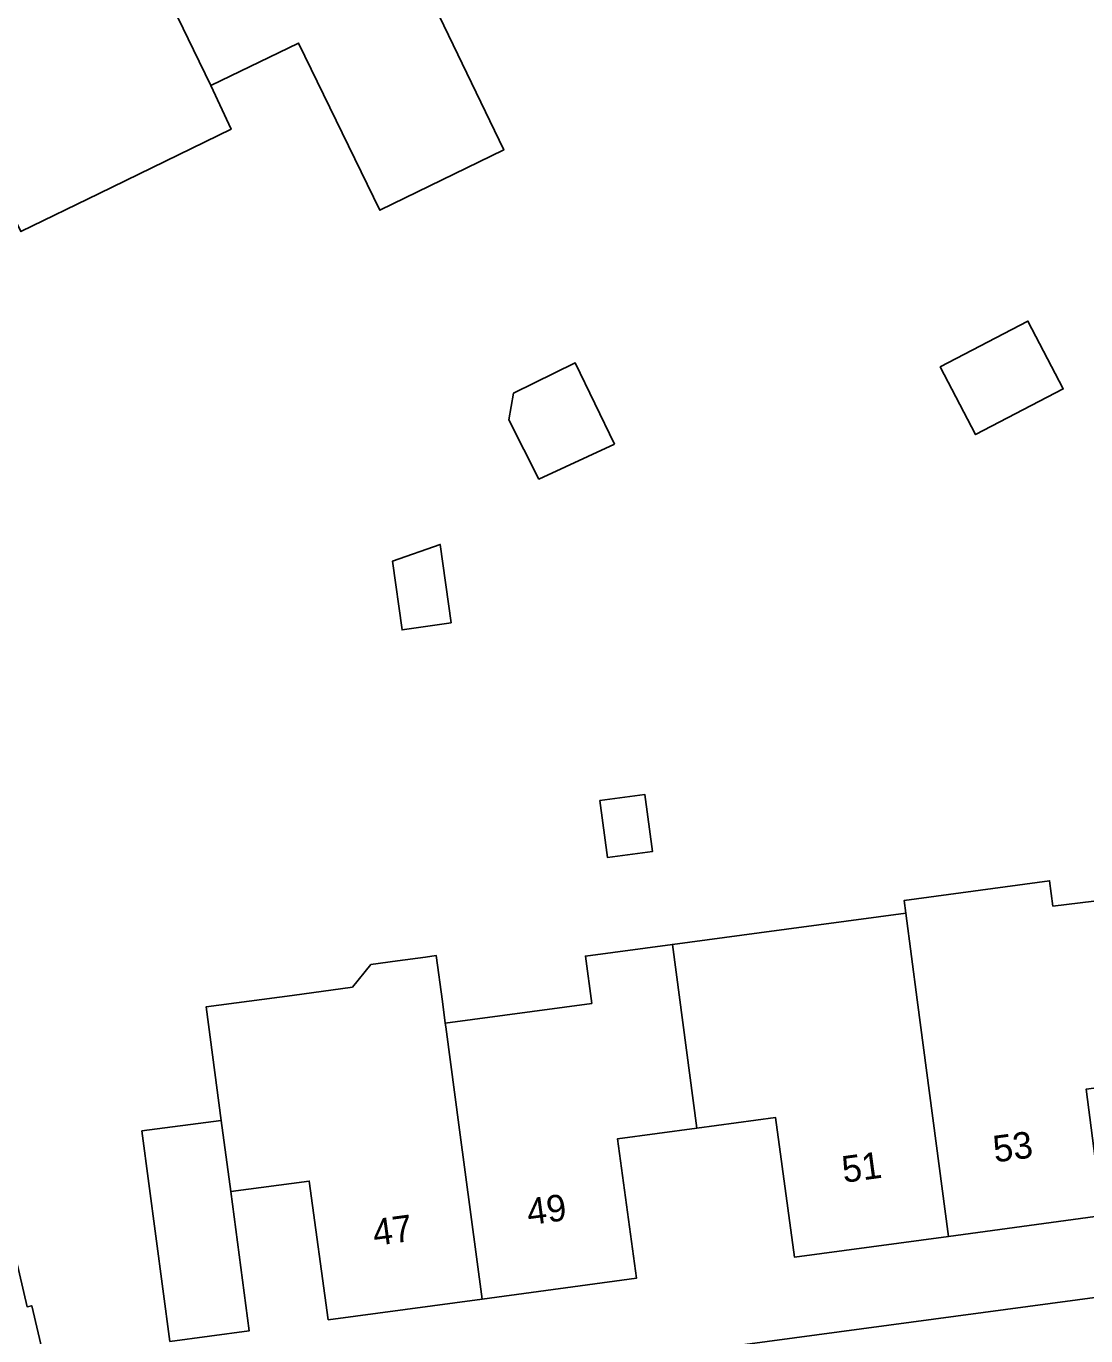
# Model space of a CAD drawing. Extents: x 163426 to 164192, y 380329 to 381641.
# Drawn here: x 163600.88 to 163640.74, y 381284.84 to 381334.12 of the extents above; entities that cross this region are included whole.
import ezdxf

# ---------------------------------------------------------------- set-up
doc = ezdxf.new("R2010")
doc.units = 0
for name, color, linetype in [('IMGEO_Erf', 7, 'Continuous'), ('IMGEO_Pand', 7, 'Continuous'), ('IMGEO_Pand_nummerreeks', 7, 'Continuous'), ('IMGEO_Voetpad_open', 7, 'Continuous')]:
    doc.layers.add(name, color=color, linetype=linetype)

msp = doc.modelspace()

# ---------------------------------------------------------------- linework, layer by layer
at = {"layer": 'IMGEO_Erf'}
for points in [[(163616.584, 381334.147), (163618.845, 381329.461), (163614.183, 381327.191), (163611.124, 381333.487), (163607.829, 381331.883), (163608.59, 381330.244), (163603.63, 381327.83), (163600.68, 381326.39)], [(163641.37, 381289.36), (163635.572, 381288.579), (163629.776, 381287.799), (163629.07, 381293.049), (163626.1, 381292.65), (163623.127, 381292.25), (163623.833, 381287), (163618.037, 381286.22), (163612.24, 381285.44), (163611.53, 381290.66), (163608.572, 381290.266), (163609.266, 381285.022), (163606.284, 381284.627), (163605.236, 381292.548), (163608.214, 381292.942), (163607.65, 381297.21), (163610.885, 381297.648), (163613.152, 381297.952), (163613.845, 381298.813), (163614.843, 381298.947), (163615.896, 381299.088), (163616.304, 381299.143), (163616.535, 381297.422), (163616.645, 381296.602), (163622.155, 381297.342), (163621.916, 381299.124), (163625.186, 381299.562), (163628.45, 381300), (163633.97, 381300.741), (163633.908, 381301.222), (163639.372, 381301.961), (163639.5, 381301.01), (163642.07, 381301.32)], [(163599.791, 381290.734), (163600.912, 381285.927), (163601.092, 381285.969), (163601.704, 381283.347)], [(163588.634, 381279.227), (163596.717, 381280.313), (163605.786, 381281.532), (163642.098, 381286.411), (163645.301, 381286.841)]]:
    msp.add_lwpolyline(points, dxfattribs=at)
for points in [[(163639.888, 381320.472), (163636.593, 381318.749), (163635.261, 381321.298), (163638.556, 381323.021)], [(163623.007, 381318.389), (163620.168, 381317.076), (163619.036, 381319.31), (163619.216, 381320.316), (163621.535, 381321.449)], [(163616.871, 381311.662), (163615.022, 381311.401), (163614.658, 381313.987), (163616.455, 381314.619)], [(163624.156, 381305.204), (163624.44, 381303.062), (163622.746, 381302.835), (163622.463, 381304.977)]]:
    msp.add_lwpolyline(points, close=True, dxfattribs=at)
at = {"layer": 'IMGEO_Pand'}
for points in [[(163613.542, 381340.434), (163610.85, 381339.112), (163608.422, 381344.055), (163607.84, 381345.24), (163605.28, 381344), (163605.938, 381342.655), (163603.253, 381341.342), (163607.177, 381333.232), (163607.829, 381331.883), (163611.124, 381333.487), (163614.183, 381327.191), (163618.845, 381329.461), (163616.584, 381334.147)], [(163603.253, 381341.342), (163600.558, 381340.025), (163599.9, 381341.37), (163597.36, 381340.12), (163600.326, 381333.998), (163597.625, 381332.689), (163598.149, 381331.624), (163600.68, 381326.39), (163603.63, 381327.83), (163608.59, 381330.244), (163607.829, 381331.883), (163607.177, 381333.232)], [(163635.261, 381321.298), (163636.593, 381318.749), (163639.888, 381320.472), (163638.556, 381323.021)], [(163623.007, 381318.389), (163621.535, 381321.449), (163619.216, 381320.316), (163619.036, 381319.31), (163620.168, 381317.076)], [(163616.871, 381311.662), (163616.455, 381314.619), (163614.658, 381313.987), (163615.022, 381311.401)], [(163622.463, 381304.977), (163622.746, 381302.835), (163624.44, 381303.062), (163624.156, 381305.204)], [(163642.07, 381301.32), (163639.5, 381301.01), (163639.372, 381301.961), (163633.908, 381301.222), (163633.97, 381300.741), (163634.391, 381297.478), (163635.572, 381288.579), (163641.37, 381289.36), (163640.75, 381294.12), (163644.78, 381294.65)], [(163634.391, 381297.478), (163633.97, 381300.741), (163628.45, 381300), (163625.186, 381299.562), (163626.1, 381292.65), (163629.07, 381293.049), (163629.776, 381287.799), (163635.572, 381288.579)], [(163625.186, 381299.562), (163621.916, 381299.124), (163622.155, 381297.342), (163616.645, 381296.602), (163616.664, 381296.459), (163617.184, 381292.585), (163618.037, 381286.22), (163623.833, 381287), (163623.127, 381292.25), (163626.1, 381292.65)], [(163616.645, 381296.602), (163616.535, 381297.422), (163616.304, 381299.143), (163615.896, 381299.088), (163614.843, 381298.947), (163613.845, 381298.813), (163613.152, 381297.952), (163610.885, 381297.648), (163607.65, 381297.21), (163608.214, 381292.942), (163608.572, 381290.266), (163611.53, 381290.66), (163612.24, 381285.44), (163618.037, 381286.22), (163617.184, 381292.585), (163616.664, 381296.459)], [(163608.214, 381292.942), (163605.236, 381292.548), (163606.284, 381284.627), (163609.266, 381285.022), (163608.572, 381290.266)], [(163599.791, 381290.734), (163599.972, 381290.776), (163599.826, 381291.4), (163596.991, 381290.736), (163588.216, 381288.682), (163588.9, 381285.762), (163587.44, 381285.42), (163588.07, 381282.65), (163595.156, 381284.302), (163595.705, 381281.948), (163601.704, 381283.347), (163601.092, 381285.969), (163600.912, 381285.927)]]:
    msp.add_lwpolyline(points, close=True, dxfattribs=at)
at = {"layer": 'IMGEO_Voetpad_open'}
msp.add_lwpolyline([(163645.301, 381286.841), (163642.098, 381286.411), (163605.786, 381281.532), (163596.717, 381280.313), (163588.634, 381279.227)], dxfattribs=at)

# ---------------------------------------------------------------- texts
at = {"layer": 'IMGEO_Pand_nummerreeks'}
for s, p in [('53', (163637.317, 381291.357)), ('51', (163631.632, 381290.591)), ('49', (163619.78, 381288.997)), ('47', (163613.984, 381288.217))]:
    msp.add_text(s, height=1, rotation=7.6662, dxfattribs=at).set_placement(p)

doc.saveas('drawing.dxf')
